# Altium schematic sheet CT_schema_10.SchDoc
size 274 x 160 mm
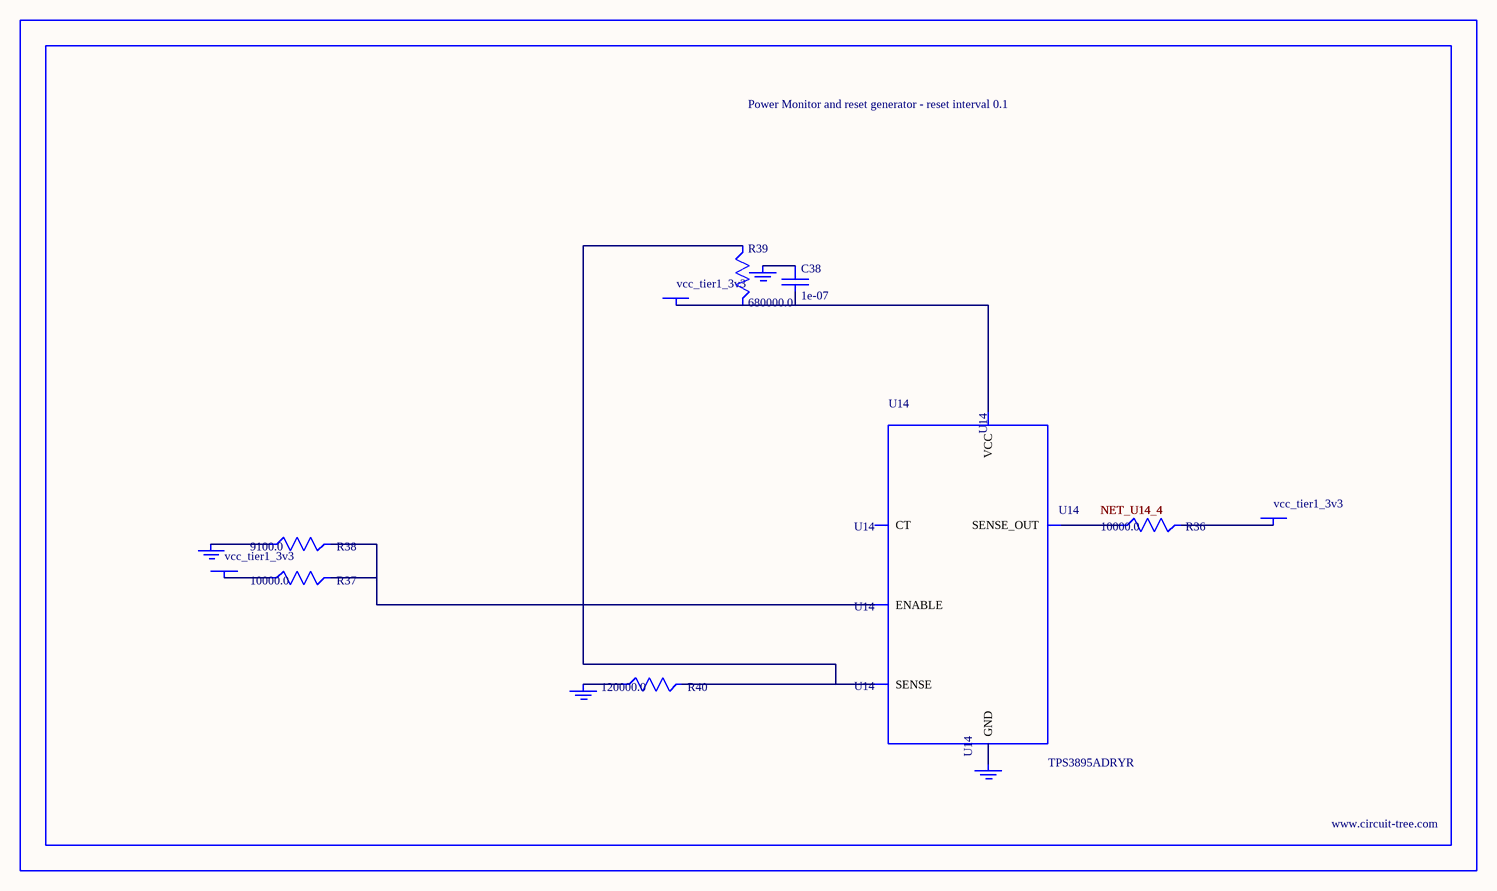
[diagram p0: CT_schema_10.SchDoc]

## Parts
BORDER9  (no value)
C38  1e-07  [C0402]
GND_INSTANCE_9_0  (no value)
GND_INSTANCE_9_1  (no value)
GND_INSTANCE_9_2  (no value)
GND_INSTANCE_9_3  (no value)
POWER_INSTANCE_9_0  vcc_tier1_3v3
POWER_INSTANCE_9_1  vcc_tier1_3v3
POWER_INSTANCE_9_2  vcc_tier1_3v3
R36  10000.0  [R0603]
R37  10000.0  [R0603]
R38  9100.0  [R0603]
R39  680000.0  [R0603]
R40  120000.0  [R0603]
U14  TPS3895ADRYR  [SON-6]

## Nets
NetC38_1: C38.1 GND_INSTANCE_9_2.0(GND)
NetC38_2: C38.2 POWER_INSTANCE_9_2.0(PWR) R39.2 U14.6(VCC)
NetGND_INSTANCE_9_0_0: GND_INSTANCE_9_0.0(GND) R38.1
NetGND_INSTANCE_9_1_0: GND_INSTANCE_9_1.0(GND) R40.1
NetGND_INSTANCE_9_3_0: GND_INSTANCE_9_3.0(GND) U14.2(GND)
NetPOWER_INSTANCE_9_0_0: POWER_INSTANCE_9_0.0(PWR) R37.1
NetPOWER_INSTANCE_9_1_0: POWER_INSTANCE_9_1.0(PWR) R36.2
NetR36_1: R36.1 U14.4(SENSE_OUT)
NetR37_2: R37.2 R38.2 U14.1(ENABLE)
NetR39_1: R39.1 R40.2 U14.3(SENSE)

Not connected (* = marked no-connect by the designer): U14 5(CT)

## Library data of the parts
BORDER9 = BORDER_PAGE9
C38 = C0402C104K3RACTU
GND_INSTANCE_9_0-GND_INSTANCE_9_3 = GND
POWER_INSTANCE_9_0-POWER_INSTANCE_9_2 = PWR
R36 R37 = RC0603JR-0710KL
R38 = RC0603JR-079K1L
R39 = RC0603JR-07680KL
R40 = RC0603JR-07120KL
